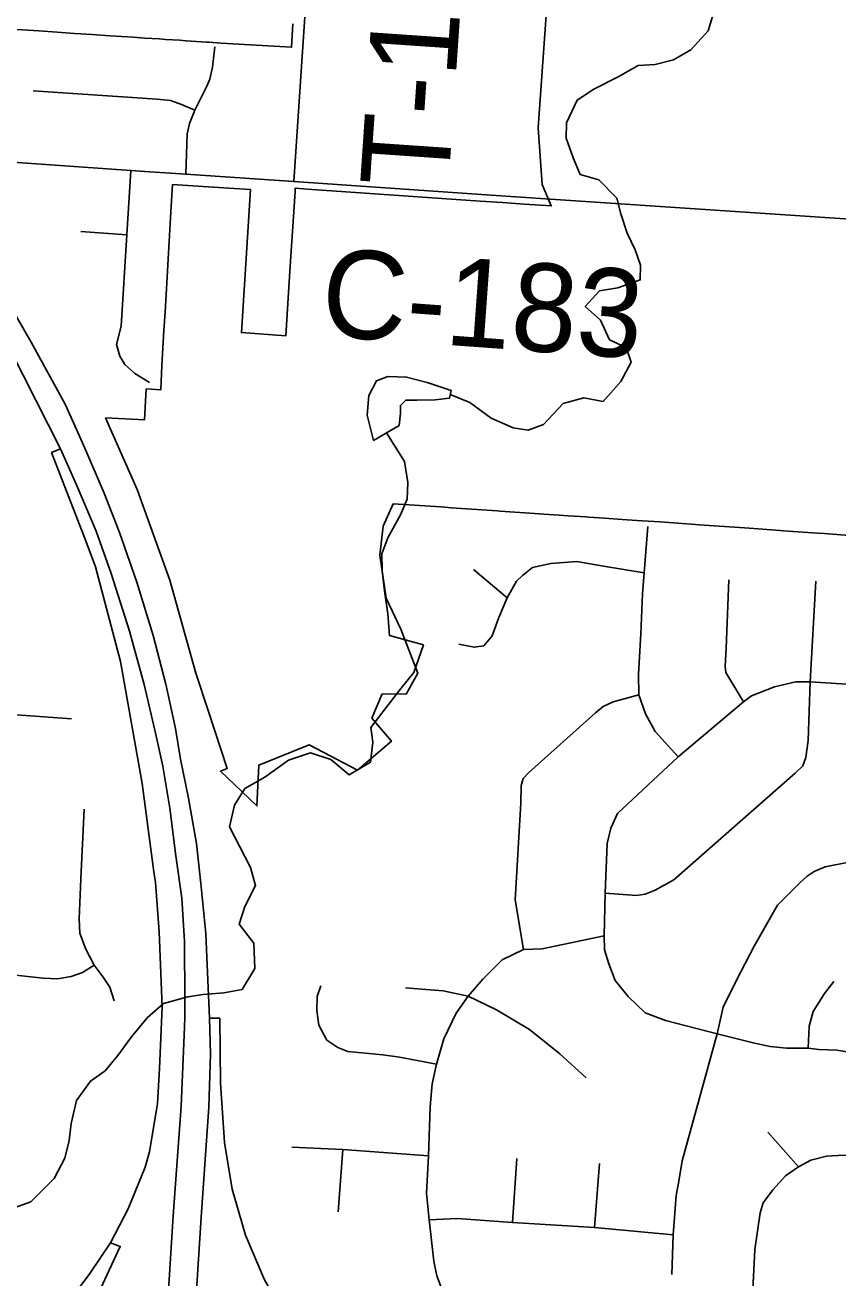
# Model space of a CAD drawing. Extents: x 0 to 34, y 0 to 22.
# Drawn here: x 6.003 to 6.527, y 18.131 to 18.938 of the extents above; entities that cross this region are included whole.
import ezdxf

# ---------------------------------------------------------------- set-up
doc = ezdxf.new("R2010")
doc.units = 0
for name, color, linetype in [('GM_X_Corporation', 7, 'Continuous'), ('GM_X_County_Road', 7, 'Continuous'), ('GM_X_County_Road_Text', 7, 'Continuous'), ('GM_X_Interchange_Ramps', 7, 'Continuous'), ('GM_X_Interstate_Route', 7, 'Continuous'), ('GM_X_Minor_Lake', 7, 'Continuous'), ('GM_X_Minor_River', 7, 'Continuous'), ('GM_X_Township_Road', 7, 'Continuous'), ('GM_X_Township_Road_Text', 7, 'Continuous')]:
    doc.layers.add(name, color=color, linetype=linetype)

msp = doc.modelspace()

# ---------------------------------------------------------------- linework, layer by layer
at = {"layer": 'GM_X_Corporation'}
for points in [[(6.34152, 18.98379), (6.33345, 18.87166), (6.33617, 18.83512), (6.34196, 18.82143), (6.32453, 18.82262), (6.31058, 18.82358), (6.29623, 18.82456), (6.2066, 18.8307), (6.18776, 18.83199), (6.17708, 18.83273), (6.17694, 18.83068), (6.17361, 18.77944), (6.1709, 18.73771), (6.14236, 18.73979), (6.14818, 18.83188), (6.13424, 18.83279), (6.09801, 18.83523), (6.09718, 18.82106), (6.09653, 18.81002), (6.09585, 18.79846), (6.0952, 18.78734), (6.0945, 18.7756), (6.09384, 18.76428), (6.09318, 18.75306), (6.09248, 18.74113), (6.09115, 18.71859), (6.09039, 18.70292), (6.08092, 18.70353), (6.08056, 18.69567), (6.08002, 18.68364), (6.05485, 18.68489), (6.07518, 18.63881), (6.09626, 18.58028), (6.11307, 18.52038), (6.12093, 18.49648), (6.13324, 18.45907), (6.12889, 18.45721), (6.14256, 18.44416), (6.15234, 18.43492), (6.15366, 18.46119), (6.18609, 18.47422), (6.21717, 18.45793), (6.23894, 18.47653), (6.22644, 18.49136), (6.23307, 18.50707), (6.24846, 18.50698), (6.25603, 18.52053), (6.24506, 18.54878), (6.23553, 18.56877), (6.23156, 18.59639), (6.23368, 18.61518), (6.24012, 18.62959), (6.27089, 18.62749), (6.27331, 18.62731), (6.27755, 18.62702), (6.29409, 18.62589), (6.30721, 18.62499), (6.30911, 18.62486), (6.31849, 18.62421), (6.3281, 18.62355), (6.33709, 18.62294), (6.34714, 18.62225), (6.35276, 18.62186), (6.35667, 18.6216), (6.36429, 18.62107), (6.36621, 18.62094), (6.37619, 18.62027), (6.3877, 18.61947), (6.40059, 18.61859), (6.41203, 18.61781), (6.43478, 18.61622), (6.4372, 18.61605), (6.46635, 18.61397), (6.47246, 18.61354), (6.4895, 18.61232), (6.4916, 18.61217), (6.51342, 18.61061), (6.51797, 18.61029), (6.53378, 18.60916)], [(5.98364, 18.93595), (6.01191, 18.93408), (6.02361, 18.9333), (6.03492, 18.93255), (6.04633, 18.93179), (6.05769, 18.93104), (6.06906, 18.93028), (6.07256, 18.93005), (6.08023, 18.92954), (6.08942, 18.92893), (6.09354, 18.92866), (6.10263, 18.92806), (6.1067, 18.92779), (6.11991, 18.92691), (6.12166, 18.9268), (6.12934, 18.9263), (6.14827, 18.92517), (6.15184, 18.92495), (6.17464, 18.92358), (6.17555, 18.93871)]]:
    msp.add_lwpolyline(points, dxfattribs=at)
at = {"layer": 'GM_X_County_Road'}
for points in [[(5.80515, 18.86234), (5.90861, 18.8556), (5.92792, 18.85423), (6.07124, 18.84411), (6.08009, 18.84353)], [(6.08009, 18.84353), (6.10662, 18.84177), (6.17606, 18.83709), (6.30332, 18.82829)], [(6.30332, 18.82829), (6.34149, 18.82565), (6.68224, 18.80302), (6.89881, 18.78652)]]:
    msp.add_lwpolyline(points, dxfattribs=at)
at = {"layer": 'GM_X_Interchange_Ramps'}
for points in [[(6.02585, 18.665), (6.02008, 18.6625), (6.0423, 18.60495), (6.04845, 18.58901), (6.06443, 18.52799), (6.07847, 18.44927), (6.08602, 18.39245), (6.08693, 18.38564), (6.08934, 18.35377), (6.09142, 18.30558), (6.08952, 18.26582), (6.08832, 18.24315), (6.08314, 18.21201), (6.0804, 18.2023), (6.06944, 18.17528), (6.05813, 18.15338)], [(6.29844, 17.99655), (6.28156, 18.00414), (6.26888, 18.01109), (6.25663, 18.01851), (6.23303, 18.0354), (6.21122, 18.05471), (6.19073, 18.07734), (6.18918, 18.07947), (6.17265, 18.10237), (6.15731, 18.12969), (6.14508, 18.15838), (6.13638, 18.18797), (6.1314, 18.21801), (6.12882, 18.25635), (6.12843, 18.29813), (6.1218, 18.29821)], [(6.05813, 18.15338), (6.04473, 18.13378), (6.02087, 18.10181), (6.00707, 18.08714), (5.99197, 18.07356), (5.97707, 18.06196), (5.94336, 18.03918), (5.92541, 18.03086), (5.90701, 18.02342), (5.88796, 18.01707), (5.86869, 18.01247), (5.85928, 18.01073), (5.82922, 18.00662), (5.79781, 18.00563), (5.79758, 18.00039)], [(6.05813, 18.15338), (6.06433, 18.15119), (6.04594, 18.11191), (6.0231, 18.06584), (6.01973, 18.05902), (6.01254, 18.03145), (6.01112, 18.0213), (6.00962, 18.01019), (6.01171, 17.98623), (6.01334, 17.97723), (6.01494, 17.96769)]]:
    msp.add_lwpolyline(points, dxfattribs=at)
at = {"layer": 'GM_X_Interstate_Route'}
msp.add_line((6.10575, 18.34755), (6.10592, 18.30998), dxfattribs=at)
for points in [[(5.75777, 19.00562), (5.76557, 18.99961), (5.80417, 18.96649), (5.83861, 18.93425), (5.87677, 18.89302), (5.90861, 18.8556), (5.96626, 18.77436), (5.99389, 18.72808), (6.02585, 18.665), (6.03622, 18.64167), (6.04872, 18.61184), (6.05838, 18.58464), (6.07022, 18.54757), (6.07965, 18.51314), (6.08733, 18.4809), (6.09171, 18.4605), (6.09632, 18.43352), (6.10005, 18.40282), (6.104, 18.3754), (6.10575, 18.34755)], [(5.98056, 18.77923), (6.00688, 18.73361), (6.02903, 18.69326), (6.04153, 18.6654), (6.05403, 18.63645), (6.0639, 18.61101), (6.07509, 18.57899), (6.08562, 18.54477), (6.09373, 18.51341), (6.09987, 18.48489), (6.10322, 18.46507), (6.10821, 18.43993), (6.11347, 18.41076), (6.11632, 18.38488), (6.11939, 18.35264), (6.12006, 18.33752)], [(6.12006, 18.33752), (6.1218, 18.29821), (6.12246, 18.275), (6.12145, 18.24092), (6.11641, 18.17008), (6.11125, 18.08886), (6.1075, 18.02995), (6.10541, 17.99701), (6.10444, 17.97852), (6.10397, 17.96954), (6.10094, 17.92423)], [(6.10592, 18.30998), (6.10597, 18.29842), (6.10549, 18.28723), (6.10356, 18.24161), (6.09851, 18.17077), (6.0896, 18.03061), (6.08721, 17.99224)]]:
    msp.add_lwpolyline(points, dxfattribs=at)
at = {"layer": 'GM_X_Minor_Lake'}
for points in [[(6.2439, 18.68002), (6.24474, 18.68798), (6.24479, 18.69291), (6.24824, 18.6963), (6.25545, 18.69623), (6.26721, 18.69649), (6.27633, 18.69754), (6.27752, 18.70246), (6.26201, 18.70755), (6.24876, 18.71109), (6.23662, 18.71159), (6.22938, 18.70863), (6.22436, 18.69919), (6.22347, 18.68667), (6.22749, 18.67031)], [(6.22749, 18.67031), (6.2439, 18.68002)]]:
    msp.add_lwpolyline(points, dxfattribs=at)
at = {"layer": 'GM_X_Minor_River'}
for points in [[(6.44649, 18.94561), (6.44296, 18.93425), (6.43183, 18.92184), (6.42077, 18.9155), (6.40898, 18.91258), (6.39796, 18.91192), (6.38499, 18.90446), (6.36935, 18.89665), (6.35866, 18.88954), (6.35168, 18.87481), (6.35158, 18.86494), (6.35602, 18.85237), (6.36047, 18.8417), (6.37258, 18.83816), (6.38423, 18.82628), (6.38679, 18.81639), (6.39084, 18.80382), (6.39605, 18.79314), (6.39937, 18.78324), (6.39928, 18.77375), (6.3848, 18.76858), (6.37302, 18.7668), (6.36382, 18.75664), (6.3736, 18.74782), (6.37955, 18.73523), (6.39012, 18.73019), (6.39345, 18.72067), (6.38687, 18.70821), (6.37536, 18.69542), (6.36286, 18.69782), (6.34955, 18.69415), (6.33689, 18.68062), (6.32699, 18.67692), (6.31751, 18.67853), (6.30315, 18.68474), (6.28959, 18.69475), (6.27693, 18.70001)], [(6.2359, 18.67528), (6.24747, 18.65683), (6.24962, 18.64314), (6.24913, 18.63252), (6.24486, 18.62231), (6.23675, 18.60759), (6.23285, 18.59738), (6.23312, 18.58637), (6.23451, 18.57345), (6.23665, 18.55863), (6.23765, 18.54458), (6.24787, 18.54182), (6.25961, 18.53866), (6.25336, 18.52089), (6.24529, 18.51072), (6.23568, 18.49829), (6.22569, 18.48548), (6.22712, 18.47598), (6.22547, 18.46309), (6.21173, 18.45487), (6.20006, 18.46486), (6.18682, 18.46916), (6.17273, 18.46437), (6.15745, 18.45351), (6.14447, 18.44605), (6.13792, 18.43549), (6.13474, 18.42147), (6.14107, 18.40889), (6.14815, 18.39515), (6.15145, 18.38373), (6.14449, 18.37013), (6.14096, 18.35878), (6.15033, 18.34654), (6.15093, 18.33022), (6.14283, 18.31663), (6.13105, 18.31447), (6.11775, 18.31346), (6.10787, 18.31204), (6.09227, 18.30764), (6.08193, 18.29864), (6.07157, 18.28621), (6.06272, 18.27416), (6.05465, 18.26437), (6.0451, 18.25763), (6.03625, 18.24519), (6.03269, 18.23042), (6.03145, 18.21943), (6.02868, 18.20807), (6.02172, 18.19485), (6.00677, 18.17981), (5.99306, 18.17502)]]:
    msp.add_lwpolyline(points, dxfattribs=at)
at = {"layer": 'GM_X_Township_Road'}
for p, q in [((6.03899, 18.80484), (6.06864, 18.80275)), ((6.29192, 18.58726), (6.31348, 18.56891)), ((6.50865, 18.51474), (6.51227, 18.5797)), ((6.44069, 18.25856), (6.44891, 18.28813)), ((6.50118, 18.20254), (6.48151, 18.22468)), ((6.20466, 18.1734), (6.20762, 18.21353)), ((6.31697, 18.16666), (6.31967, 18.20787)), ((6.36976, 18.16343), (6.37299, 18.20464))]:
    msp.add_line(p, q, dxfattribs=at)
for points in [[(6.17606, 18.83709), (6.18728, 19.00466), (6.19143, 19.05734), (6.19304, 19.07808), (6.19419, 19.09814), (6.19227, 19.11256), (6.18824, 19.12939)], [(6.10662, 18.84177), (6.10739, 18.86778), (6.10895, 18.87455), (6.11234, 18.88313), (6.12014, 18.89848), (6.12213, 18.90313), (6.12379, 18.9107), (6.12535, 18.92397)], [(6.0083, 18.89561), (6.08815, 18.89015), (6.09673, 18.88937), (6.10375, 18.88677), (6.11234, 18.88313)], [(6.08312, 18.70755), (6.07371, 18.7134), (6.06733, 18.71921), (6.06399, 18.72457), (6.06182, 18.73221), (6.065, 18.74397), (6.06864, 18.80275), (6.07124, 18.84411)], [(6.42368, 18.46649), (6.40897, 18.48281), (6.40267, 18.49431), (6.39829, 18.50655), (6.39811, 18.51986), (6.39964, 18.54569), (6.40078, 18.57152), (6.40182, 18.58512), (6.40408, 18.61481)], [(6.28246, 18.53912), (6.29232, 18.53707), (6.29842, 18.53811), (6.30383, 18.54449), (6.30818, 18.55621), (6.31348, 18.56891), (6.31955, 18.57961), (6.32341, 18.58335), (6.32995, 18.58857), (6.34177, 18.59105), (6.35851, 18.59232), (6.37558, 18.58939), (6.40182, 18.58512)], [(6.46574, 18.50202), (6.45439, 18.52089), (6.45406, 18.5247), (6.45462, 18.53648), (6.45641, 18.58055)], [(6.37595, 18.3513), (6.37661, 18.37871), (6.37787, 18.41068), (6.3803, 18.42052), (6.38462, 18.42996), (6.42368, 18.46649), (6.46574, 18.50202), (6.47088, 18.50582), (6.4858, 18.51167), (6.49953, 18.51488), (6.50865, 18.51474), (6.56265, 18.5113), (6.62066, 18.50691), (6.65713, 18.50563), (6.67351, 18.50727), (6.6892, 18.52002), (6.70696, 18.52298), (6.71649, 18.52314), (6.72685, 18.5215), (6.77798, 18.50325), (6.7913, 18.49881)], [(6.37661, 18.37871), (6.39676, 18.37731), (6.40247, 18.37798), (6.40898, 18.38055), (6.42086, 18.38721), (6.49904, 18.45596), (6.50405, 18.46083), (6.50603, 18.46612), (6.50733, 18.47713), (6.50865, 18.51474)], [(5.79688, 18.45699), (5.79439, 18.47527), (5.79563, 18.48566), (5.79896, 18.49272), (5.80685, 18.50061), (5.8214, 18.5056), (5.83552, 18.50477), (5.94064, 18.49812), (5.99174, 18.49396), (6.03287, 18.49106)], [(6.32411, 18.34249), (6.3188, 18.37432), (6.32238, 18.43662), (6.32255, 18.44802), (6.32375, 18.45256), (6.32723, 18.45631), (6.37038, 18.49481), (6.37538, 18.49892), (6.38188, 18.50186), (6.39829, 18.50655)], [(6.0605, 18.30929), (6.05759, 18.31822), (6.05343, 18.32466), (6.04762, 18.33235), (6.04201, 18.34315), (6.03827, 18.35291), (6.03786, 18.36226), (6.03889, 18.38802), (6.04118, 18.43289)], [(6.44891, 18.28813), (6.4527, 18.30519), (6.46154, 18.32319), (6.4726, 18.34466), (6.48776, 18.37088), (6.50179, 18.38521), (6.5068, 18.38969), (6.5114, 18.39266), (6.51829, 18.3956), (6.53354, 18.39878), (6.55173, 18.39807), (6.56007, 18.39642), (6.59726, 18.38907), (6.60253, 18.38594), (6.6089, 18.38014), (6.61148, 18.37439), (6.61472, 18.36267), (6.61504, 18.35066), (6.62056, 18.32777)], [(5.64897, 18.3473), (5.67556, 18.34938), (5.698, 18.35021), (5.71088, 18.35021), (5.73581, 18.34979), (5.81724, 18.34232), (5.87104, 18.33754), (5.89514, 18.33525), (5.92568, 18.33297), (5.95144, 18.32985), (5.9828, 18.32736), (6.01459, 18.32404), (6.02394, 18.32362), (6.03266, 18.32508), (6.03993, 18.32757), (6.04762, 18.33235)], [(6.26627, 18.14167), (6.26338, 18.16828), (6.26162, 18.18549), (6.26284, 18.20949), (6.26391, 18.241), (6.26526, 18.25581), (6.26796, 18.26847), (6.2728, 18.2849), (6.28061, 18.30133), (6.28842, 18.31238), (6.29789, 18.32332), (6.31024, 18.33567), (6.32411, 18.34249), (6.33619, 18.34288), (6.37595, 18.3513)], [(6.37595, 18.3513), (6.37627, 18.34214), (6.37911, 18.3333), (6.38321, 18.32255), (6.39143, 18.31213), (6.40248, 18.30171), (6.41543, 18.29665), (6.44891, 18.28813), (6.47196, 18.28229), (6.48286, 18.27992), (6.49344, 18.27897), (6.50734, 18.27897), (6.51429, 18.27803), (6.52581, 18.27755), (6.5375, 18.27565)], [(6.50734, 18.27897), (6.50797, 18.29303), (6.51066, 18.3025), (6.51792, 18.31403), (6.52392, 18.32176)], [(6.19361, 18.3191), (6.19119, 18.3121), (6.19092, 18.30322), (6.19227, 18.29379), (6.19739, 18.28409), (6.20439, 18.27924), (6.21086, 18.27682), (6.23348, 18.27466), (6.24425, 18.27305), (6.25557, 18.2709), (6.26796, 18.26847)], [(6.24802, 18.31776), (6.26122, 18.31668), (6.27226, 18.31587), (6.28842, 18.31238)], [(6.28842, 18.31238), (6.30674, 18.30348), (6.32802, 18.29083), (6.3474, 18.27521), (6.36437, 18.25985)], [(6.41967, 18.13316), (6.42049, 18.15868), (6.42241, 18.18393), (6.42406, 18.19326), (6.42617, 18.20633), (6.44069, 18.25856)], [(6.45901, 18.06768), (6.46581, 18.09263), (6.4707, 18.11252), (6.47149, 18.11884), (6.47306, 18.14911), (6.47654, 18.17285), (6.47844, 18.17933), (6.4846, 18.18769), (6.49281, 18.1967), (6.50118, 18.20254), (6.50908, 18.2068), (6.51934, 18.20933), (6.53039, 18.20996), (6.55219, 18.20822), (6.5615, 18.20822), (6.58693, 18.22843)], [(6.17476, 18.21514), (6.20762, 18.21353), (6.26284, 18.20949)], [(6.26338, 18.16828), (6.28142, 18.16909), (6.31697, 18.16666), (6.36976, 18.16343), (6.42049, 18.15868)], [(6.26627, 18.14167), (6.26833, 18.1322), (6.27149, 18.12356), (6.27931, 18.1108), (6.2834, 18.10618), (6.2933, 18.09749), (6.30414, 18.09227), (6.31539, 18.08966), (6.36177, 18.085), (6.39759, 18.0811), (6.41875, 18.07668), (6.45901, 18.06768), (6.58377, 18.03713), (6.59961, 18.03416), (6.62237, 18.03194), (6.65329, 18.02971), (6.6552, 18.02957)]]:
    msp.add_lwpolyline(points, dxfattribs=at)

# ---------------------------------------------------------------- texts
at = {"layer": 'GM_X_County_Road_Text'}
msp.add_text('C-183', height=0.056818, rotation=355.87541, dxfattribs=at).set_placement((6.19254, 18.73781))
at = {"layer": 'GM_X_Township_Road_Text'}
msp.add_text('T-184', height=0.056818, rotation=86.07407, dxfattribs=at).set_placement((6.27552, 18.83202))

doc.saveas('drawing.dxf')
